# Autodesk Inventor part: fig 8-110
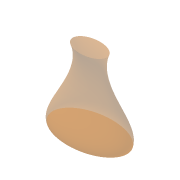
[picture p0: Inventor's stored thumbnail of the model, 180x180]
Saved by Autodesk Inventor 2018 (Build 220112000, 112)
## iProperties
Created: 2004-05
Part Number: fig 8-110
Document SubType Name: Modeling
Designer: CADCIM Technologies
Manufacturer: Standard
Standards Organization: Custom
Density: 1 g/cm^3
Material: Generic
Appearance: Default
Author: CADCIM Technologies
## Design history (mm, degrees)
sketch "Sketch4"
  geometry: 1 further point; 1 other entity
  constraints: 2 other
workplane "Work Plane2"
sketch "Sketch5"
  geometry: 1 further point; 1 other entity
  constraints: 2 other
feature "LoftSrf1" sketch "Sketch5" dims "d4" = 20, "d5" = 110 deg, "d6" = 40, "d7" = 70 deg
patch "Boundary Patch1" dims "d8" = 0, "d9" = 0
patch "Boundary Patch2" dims "d10" = 0, "d11" = 0
patch "Boundary Patch3" dims "d12" = 0, "d13" = 0
body "Srf1"
body "Srf2"
body "Srf3"
body "Srf4"
other parameters: "d3" = 33.5
